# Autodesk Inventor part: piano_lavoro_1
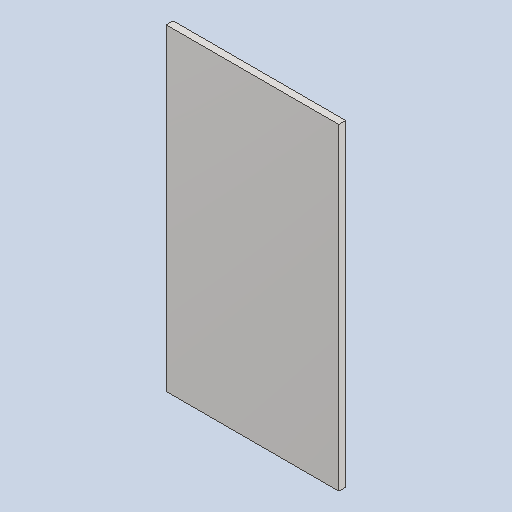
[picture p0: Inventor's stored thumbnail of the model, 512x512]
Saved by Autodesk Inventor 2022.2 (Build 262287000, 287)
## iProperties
Created: 2024-10
Part Number: piano_lavoro_1
Material: Alluminio 6061
Document SubType Name: Modeling
Designer: 18907419
Density: 2.7 g/cm^3
Appearance: Default
Author: 18907419
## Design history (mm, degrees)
feature "Solido1"
node "Solido2"
